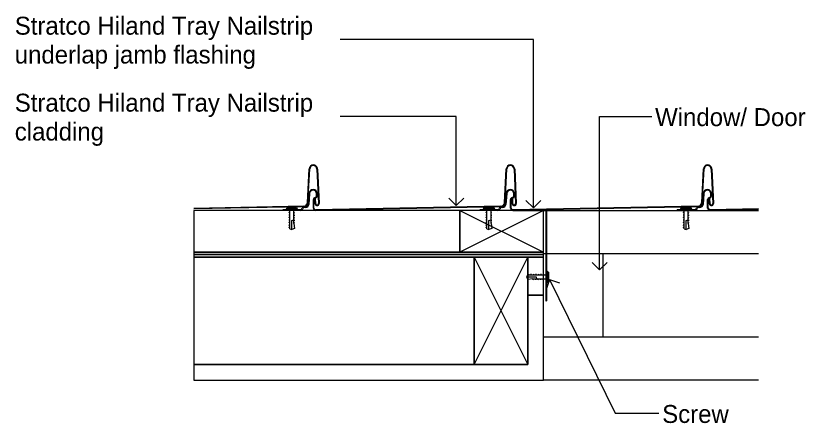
# Model space of a CAD drawing. Extents: x -2.36 to 6.66, y -3.72 to 4.13.
# Drawn here: x 5.189 to 5.85, y -2.178 to -1.837 of the extents above; entities that cross this region are included whole.
import ezdxf

# ---------------------------------------------------------------- set-up
doc = ezdxf.new("R2010")
doc.units = 0
for name, color, linetype in [('A-____-____-IDEN', 7, 'Continuous'), ('A-DETL-____-MEDM', 7, 'Continuous'), ('A-DETL-GENF-OTLN', 7, 'Continuous'), ('A-GLAZ-____-MCUT', 7, 'Continuous'), ('A-GLAZ-____-OTLN', 7, 'Continuous'), ('A-WALL-____-MCUT', 7, 'Continuous'), ('A-WALL-____-OTLN', 7, 'Continuous'), ('A-WALL-____-PATT', 7, 'Continuous'), ('A-WALL-FNSH-MCUT', 7, 'Continuous')]:
    doc.layers.add(name, color=color, linetype=linetype)

# ---------------------------------------------------------------- blocks, each defined once
blk = doc.blocks.new('Fixed - 1L _AUS_ - 1515-V21-Detail Flashings - Hiland Nailstrip Jambs')
at = {"layer": 'A-GLAZ-____-MCUT'}
for p, q in [((0.99117, 0.035), (0.99117, -0.035)), ((0.99117, 0.035), (1.04117, 0.035)), ((1.04117, -0.035), (0.99117, -0.035))]:
    blk.add_line(p, q, dxfattribs=at)
at = {"layer": 'A-GLAZ-____-OTLN'}
for p, q in [((0.86098, 0.035), (0.99117, 0.035)), ((0.99117, -0.035), (0.86098, -0.035))]:
    blk.add_line(p, q, dxfattribs=at)
blk = doc.blocks.new('DET_ST_Framing Detail Timber - 35x70 Batten-Detail Flashings - Hiland Nailstrip Jambs')
at = {"layer": 'A-DETL-____-MEDM'}
for p, q in [((0.07, 0.035), (0, 0.035)), ((0, 0.035), (0, 0)), ((0.07, 0), (0.07, 0.035)), ((0, 0), (0.07, 0))]:
    blk.add_line(p, q, dxfattribs=at)
at = {"layer": 'A-DETL-GENF-OTLN'}
for p, q in [((0, 0.035), (0.07, 0)), ((0.07, 0.035), (0, 0))]:
    blk.add_line(p, q, dxfattribs=at)
blk = doc.blocks.new('Detail Repeating_Stratco_Hiland_Tray_Nailstrip - Rib Height 38mm_165mm Coverage-V22-Detail Flashings - Hiland Nailstrip Jambs')
at = {"layer": 'A-DETL-____-MEDM'}
for p, q in [((1.33071, 0), (1.34557, 0)), ((1.34557, 0), (1.34557, -0.0005)), ((1.49571, 0), (1.51057, 0)), ((1.51057, 0), (1.51057, -0.0005)), ((1.27731, -0.00079), (1.31797, 0)), ((1.27731, -0.00129), (1.31798, -0.0005)), ((1.31648, -0.03459), (1.31517, -0.0057)), ((1.31698, -0.03457), (1.31567, -0.00568)), ((1.31801, -0.00561), (1.31813, -0.00979)), ((1.31851, -0.0056), (1.31863, -0.00977)), ((1.3195, -0.002), (1.3195, -0.00924)), ((1.32, -0.002), (1.32, -0.00924)), ((1.3245, -0.00635), (1.32302, -0.03464)), ((1.32314, -0.01418), (1.3238, -0.00504)), ((1.325, -0.00637), (1.32351, -0.03466)), ((1.32363, -0.01422), (1.32429, -0.00508)), ((1.32662, -0.00241), (1.32757, -0.00241)), ((1.32662, -0.00291), (1.32757, -0.00291)), ((1.328, -0.00303), (1.48297, 0)), ((1.328, -0.00353), (1.48298, -0.0005)), ((1.33071, -0.0005), (1.34557, -0.0005)), ((1.4845, -0.002), (1.4845, -0.00924)), ((1.485, -0.002), (1.485, -0.00924)), ((1.48814, -0.01418), (1.4888, -0.00504)), ((1.48863, -0.01422), (1.48929, -0.00508)), ((1.49162, -0.00241), (1.49257, -0.00241)), ((1.49162, -0.00291), (1.49257, -0.00291)), ((1.49571, -0.0005), (1.51057, -0.0005)), ((1.31679, -0.01206), (1.31679, -0.01397)), ((1.31729, -0.01206), (1.31729, -0.01397)), ((1.31863, -0.00977), (1.31813, -0.00979)), ((1.48179, -0.01206), (1.48179, -0.01397)), ((1.48229, -0.01206), (1.48229, -0.01397))]:
    blk.add_line(p, q, dxfattribs=at)
for centre, radius, start, end in [((1.318, -0.002), 0.002, 360, 90), ((1.33071, -0.0019), 0.0019, 90, 165.08957), ((1.483, -0.002), 0.002, 360, 90), ((1.49571, -0.0019), 0.0019, 90, 165.08957), ((1.31684, -0.00565), 0.00167, 91.69561, 181.73842), ((1.31684, -0.00565), 0.00117, 91.68553, 181.57145), ((1.31684, -0.00565), 0.00167, 1.72718, 91.74264), ((1.31684, -0.00565), 0.00117, 1.72718, 91.75272), ((1.318, -0.002), 0.0015, 0, 90), ((1.32662, -0.00525), 0.00283, 90, 175.86847), ((1.32662, -0.00525), 0.00233, 90, 175.86847), ((1.32799, -0.00653), 0.0035, 89.8838, 176.99932), ((1.32799, -0.00653), 0.003, 89.8838, 173.99932), ((1.32757, -0.00107), 0.00135, 270, 345.08957), ((1.32757, -0.00107), 0.00185, 270, 345.08957), ((1.33071, -0.0019), 0.0014, 90, 165.08957), ((1.483, -0.002), 0.0015, 0, 90), ((1.49162, -0.00525), 0.00283, 90, 175.86847), ((1.49162, -0.00525), 0.00233, 90, 175.86847), ((1.49257, -0.00107), 0.00135, 270, 345.08957), ((1.49257, -0.00107), 0.00185, 270, 345.08957), ((1.49571, -0.0019), 0.0014, 90, 165.08957), ((1.31869, -0.01206), 0.0019, 97.16746, 180), ((1.31869, -0.01206), 0.0014, 99.15451, 180), ((1.31856, -0.00924), 0.000939, 263.63492, 0), ((1.31856, -0.00924), 0.00144, 266.42376, 0), ((1.48369, -0.01206), 0.0019, 97.16746, 180), ((1.48369, -0.01206), 0.0014, 99.15451, 180), ((1.48356, -0.00924), 0.000939, 263.63492, 0), ((1.48356, -0.00924), 0.00144, 266.42376, 0), ((1.32022, -0.01397), 0.00342, 180, 355.86847), ((1.32022, -0.01397), 0.00292, 180, 355.86847), ((1.48522, -0.01397), 0.00342, 180, 355.86847), ((1.48522, -0.01397), 0.00292, 180, 355.86847), ((1.32, -0.03448), 0.00352, 181.72283, 271.72823), ((1.32, -0.03448), 0.00302, 181.65349, 271.72911), ((1.32, -0.03448), 0.00302, 271.71675, 356.99932), ((1.32, -0.03448), 0.00352, 271.71763, 356.99932)]:
    blk.add_arc(centre, radius, start, end, dxfattribs=at)
at = {"layer": 'A-DETL-GENF-OTLN'}
for p, q in [((1.33568, 0.01509), (1.338, 0.01594)), ((1.33625, 0.01102), (1.33568, 0.01509)), ((1.338, 0.01594), (1.338, 0.00832)), ((1.33975, 0.0153), (1.338, 0.01594)), ((1.33975, 0.0153), (1.33975, 0.00022)), ((1.33975, 0.0146), (1.3405, 0.01436)), ((1.50068, 0.01509), (1.503, 0.01594)), ((1.50125, 0.01102), (1.50068, 0.01509)), ((1.503, 0.01594), (1.503, 0.00832)), ((1.50475, 0.0153), (1.503, 0.01594)), ((1.50475, 0.0153), (1.50475, 0.00022)), ((1.50475, 0.0146), (1.5055, 0.01436)), ((1.3355, 0.01068), (1.33625, 0.01044)), ((1.3355, 0.00858), (1.33625, 0.00834)), ((1.33625, 0.01102), (1.33625, 0.00022)), ((1.338, 0.00832), (1.33625, 0.00782)), ((1.33975, 0.0125), (1.3405, 0.01226)), ((1.33975, 0.0104), (1.3405, 0.01016)), ((1.33975, 0.0083), (1.3405, 0.00807)), ((1.5005, 0.01068), (1.50125, 0.01044)), ((1.5005, 0.00858), (1.50125, 0.00834)), ((1.50125, 0.01102), (1.50125, 0.00022)), ((1.503, 0.00832), (1.50125, 0.00782)), ((1.50475, 0.0125), (1.5055, 0.01226)), ((1.50475, 0.0104), (1.5055, 0.01016)), ((1.50475, 0.0083), (1.5055, 0.00807)), ((1.3355, 0.00648), (1.33625, 0.00624)), ((1.3355, 0.00438), (1.33625, 0.00414)), ((1.3355, 0.00228), (1.33625, 0.00205)), ((1.33975, 0.00621), (1.3405, 0.00597)), ((1.33975, 0.00411), (1.3405, 0.00387)), ((1.33975, 0.00201), (1.3405, 0.00177)), ((1.5005, 0.00648), (1.50125, 0.00624)), ((1.5005, 0.00438), (1.50125, 0.00414)), ((1.5005, 0.00228), (1.50125, 0.00205)), ((1.50475, 0.00621), (1.5055, 0.00597)), ((1.50475, 0.00411), (1.5055, 0.00387)), ((1.50475, 0.00201), (1.5055, 0.00177)), ((1.33399, -0.00222), (1.33344, -0.00128)), ((1.33345, -0.00129), (1.34255, -0.00129)), ((1.3421, -0.00058), (1.3339, -0.00058)), ((1.34201, -0.00222), (1.33399, -0.00222)), ((1.34255, -0.00129), (1.34201, -0.00222)), ((1.49899, -0.00222), (1.49844, -0.00128)), ((1.49845, -0.00129), (1.50755, -0.00129)), ((1.5071, -0.00058), (1.4989, -0.00058)), ((1.50701, -0.00222), (1.49899, -0.00222)), ((1.50755, -0.00129), (1.50701, -0.00222))]:
    blk.add_line(p, q, dxfattribs=at)
for centre, radius, start, end in [((1.33545, 0.00022), 0.0008, 270, 360), ((1.34055, 0.00022), 0.0008, 180, 270), ((1.50045, 0.00022), 0.0008, 270, 360), ((1.50555, 0.00022), 0.0008, 180, 270), ((1.3339, -0.00108), 0.0005, 90, 203.66982), ((1.3421, -0.00108), 0.0005, 336.33018, 90), ((1.4989, -0.00108), 0.0005, 90, 203.66982), ((1.5071, -0.00108), 0.0005, 336.33018, 90)]:
    blk.add_arc(centre, radius, start, end, dxfattribs=at)
blk = doc.blocks.new('Detail Repeating_Stratco_Hiland_Tray_Nailstrip - Rib Height 38mm_165mm Coverage-V23-Detail Flashings - Hiland Nailstrip Jambs')
at = {"layer": 'A-DETL-____-MEDM'}
for p, q in [((0.17571, 0), (0.19057, 0)), ((0.19057, 0), (0.19057, -0.0005)), ((-0.00352, -0.03459), (-0.00483, -0.0057)), ((-0.00302, -0.03457), (-0.00433, -0.00568)), ((-0.00199, -0.00561), (-0.00187, -0.00979)), ((-0.00149, -0.0056), (-0.00137, -0.00977)), ((0.0045, -0.00635), (0.00302, -0.03464)), ((0.005, -0.00637), (0.00351, -0.03466)), ((0.008, -0.00303), (0.16297, 0)), ((0.008, -0.00353), (0.16298, -0.0005)), ((0.16148, -0.03459), (0.16017, -0.0057)), ((0.16198, -0.03457), (0.16067, -0.00568)), ((0.16301, -0.00561), (0.16313, -0.00979)), ((0.16351, -0.0056), (0.16363, -0.00977)), ((0.1645, -0.002), (0.1645, -0.00924)), ((0.165, -0.002), (0.165, -0.00924)), ((0.1695, -0.00635), (0.16802, -0.03464)), ((0.16814, -0.01418), (0.1688, -0.00504)), ((0.17, -0.00637), (0.16851, -0.03466)), ((0.16863, -0.01422), (0.16929, -0.00508)), ((0.17162, -0.00241), (0.17257, -0.00241)), ((0.17162, -0.00291), (0.17257, -0.00291)), ((0.173, -0.00303), (0.26495, -0.00123)), ((0.173, -0.00353), (0.26495, -0.00173)), ((0.17571, -0.0005), (0.19057, -0.0005)), ((-0.00137, -0.00977), (-0.00187, -0.00979)), ((0.16179, -0.01206), (0.16179, -0.01397)), ((0.16229, -0.01206), (0.16229, -0.01397)), ((0.16363, -0.00977), (0.16313, -0.00979))]:
    blk.add_line(p, q, dxfattribs=at)
for centre, radius, start, end in [((0.163, -0.002), 0.002, 360, 90), ((0.17571, -0.0019), 0.0019, 90, 165.08957), ((-0.00316, -0.00565), 0.00167, 91.69561, 181.73842), ((-0.00316, -0.00565), 0.00117, 91.68553, 181.57145), ((-0.00316, -0.00565), 0.00167, 1.72718, 91.74264), ((-0.00316, -0.00565), 0.00117, 1.72718, 91.75272), ((0.00799, -0.00653), 0.0035, 89.8838, 176.99932), ((0.00799, -0.00653), 0.003, 89.8838, 173.99932), ((0.16184, -0.00565), 0.00167, 91.69561, 181.73842), ((0.16184, -0.00565), 0.00117, 91.68553, 181.57145), ((0.16184, -0.00565), 0.00167, 1.72718, 91.74264), ((0.16184, -0.00565), 0.00117, 1.72718, 91.75272), ((0.163, -0.002), 0.0015, 360, 90), ((0.17162, -0.00525), 0.00283, 90, 175.86847), ((0.17162, -0.00525), 0.00233, 90, 175.86847), ((0.17299, -0.00653), 0.0035, 89.8838, 176.99932), ((0.17299, -0.00653), 0.003, 89.8838, 173.99932), ((0.17257, -0.00107), 0.00135, 270, 345.08957), ((0.17257, -0.00107), 0.00185, 270, 345.08957), ((0.17571, -0.0019), 0.0014, 90, 165.08957), ((0.16369, -0.01206), 0.0019, 97.16746, 180), ((0.16369, -0.01206), 0.0014, 99.15451, 180), ((0.16356, -0.00924), 0.000939, 263.63492, 0), ((0.16356, -0.00924), 0.00144, 266.42376, 0), ((0.16522, -0.01397), 0.00342, 180, 355.86847), ((0.16522, -0.01397), 0.00292, 180, 355.86847), ((0, -0.03448), 0.00352, 181.72283, 271.72823), ((0, -0.03448), 0.00302, 181.65349, 271.72911), ((0, -0.03448), 0.00302, 271.71675, 356.99932), ((0, -0.03448), 0.00352, 271.71763, 356.99932), ((0.165, -0.03448), 0.00352, 181.72283, 271.72823), ((0.165, -0.03448), 0.00302, 181.65349, 271.72911), ((0.165, -0.03448), 0.00302, 271.71675, 356.99932), ((0.165, -0.03448), 0.00352, 271.71763, 356.99932)]:
    blk.add_arc(centre, radius, start, end, dxfattribs=at)
at = {"layer": 'A-DETL-GENF-OTLN'}
for p, q in [((0.18068, 0.01509), (0.183, 0.01594)), ((0.18125, 0.01102), (0.18068, 0.01509)), ((0.183, 0.01594), (0.183, 0.00832)), ((0.18475, 0.0153), (0.183, 0.01594)), ((0.18475, 0.0153), (0.18475, 0.00022)), ((0.18475, 0.0146), (0.1855, 0.01436)), ((0.1805, 0.01068), (0.18125, 0.01044)), ((0.1805, 0.00858), (0.18125, 0.00834)), ((0.18125, 0.01102), (0.18125, 0.00022)), ((0.183, 0.00832), (0.18125, 0.00782)), ((0.18475, 0.0125), (0.1855, 0.01226)), ((0.18475, 0.0104), (0.1855, 0.01016)), ((0.18475, 0.0083), (0.1855, 0.00807)), ((0.1805, 0.00648), (0.18125, 0.00624)), ((0.1805, 0.00438), (0.18125, 0.00414)), ((0.1805, 0.00228), (0.18125, 0.00205)), ((0.18475, 0.00621), (0.1855, 0.00597)), ((0.18475, 0.00411), (0.1855, 0.00387)), ((0.18475, 0.00201), (0.1855, 0.00177)), ((0.17899, -0.00222), (0.17844, -0.00128)), ((0.17845, -0.00129), (0.18755, -0.00129)), ((0.1871, -0.00058), (0.1789, -0.00058)), ((0.18701, -0.00222), (0.17899, -0.00222)), ((0.18755, -0.00129), (0.18701, -0.00222))]:
    blk.add_line(p, q, dxfattribs=at)
for centre, radius, start, end in [((0.18045, 0.00022), 0.0008, 270, 360), ((0.18555, 0.00022), 0.0008, 180, 270), ((0.1789, -0.00108), 0.0005, 90, 203.66982), ((0.1871, -0.00108), 0.0005, 336.33018, 90)]:
    blk.add_arc(centre, radius, start, end, dxfattribs=at)
blk = doc.blocks.new('DET_ST_Framing Detail Timber - 45x90-Detail Flashings - Hiland Nailstrip Jambs')
at = {"layer": 'A-DETL-____-MEDM'}
for p, q in [((0.09, 0.045), (0, 0.045)), ((0, 0.045), (0, 0)), ((0.09, 0), (0.09, 0.045)), ((0, 0), (0.09, 0))]:
    blk.add_line(p, q, dxfattribs=at)
at = {"layer": 'A-DETL-GENF-OTLN'}
for p, q in [((0, 0.045), (0.09, 0)), ((0.09, 0.045), (0, 0))]:
    blk.add_line(p, q, dxfattribs=at)
blk = doc.blocks.new('DET_Screw Metal Wafer - DET_Screw Metal Wafer-Detail Flashings - Hiland Nailstrip Jambs')
at = {"layer": 'A-DETL-GENF-OTLN'}
for p, q in [((-0.00455, 0.00071), (-0.00401, 0.00164)), ((0.00455, 0.00071), (-0.00455, 0.00071)), ((-0.00401, 0.00164), (0.00401, 0.00164)), ((0.00401, 0.00164), (0.00456, 0.0007)), ((-0.0041, 0), (0.0041, 0)), ((-0.00175, -0.00259), (-0.0025, -0.00235)), ((-0.00175, -0.00468), (-0.0025, -0.00445)), ((-0.00175, -0.00678), (-0.0025, -0.00654)), ((-0.00175, -0.01588), (-0.00175, -0.0008)), ((0.00175, -0.0116), (0.00175, -0.0008)), ((0.0025, -0.00286), (0.00175, -0.00262)), ((0.0025, -0.00496), (0.00175, -0.00472)), ((-0.00175, -0.00888), (-0.0025, -0.00864)), ((-0.00175, -0.01098), (-0.0025, -0.01074)), ((-0.00175, -0.01308), (-0.0025, -0.01284)), ((0, -0.0089), (0.00175, -0.0084)), ((0, -0.01651), (0, -0.0089)), ((0.0025, -0.00706), (0.00175, -0.00682)), ((0.0025, -0.00915), (0.00175, -0.00892)), ((0.0025, -0.01125), (0.00175, -0.01102)), ((0.00175, -0.0116), (0.00232, -0.01567)), ((-0.00175, -0.01518), (-0.0025, -0.01494)), ((-0.00175, -0.01588), (0, -0.01651)), ((0.00232, -0.01567), (0, -0.01651))]:
    blk.add_line(p, q, dxfattribs=at)
for centre, radius, start, end in [((-0.0041, 0.0005), 0.0005, 156.33018, 270), ((-0.00255, -0.0008), 0.0008, 360, 90), ((0.00255, -0.0008), 0.0008, 90, 180), ((0.0041, 0.0005), 0.0005, 270, 23.66982)]:
    blk.add_arc(centre, radius, start, end, dxfattribs=at)
blk = doc.blocks.new('Detail_Stratco_Hiland_Tray_Nailstrip_Underlap Jamb - Rib Height 25mm-Detail Flashings - Hiland Nailstrip Jambs')
at = {"layer": 'A-DETL-GENF-OTLN'}
for p, q in [((-0.11272, -0.11466), (-0.11338, -0.1238)), ((-0.11222, -0.11469), (-0.11288, -0.12384)), ((-0.10638, -0.11682), (-0.10638, -0.11491)), ((-0.10588, -0.11682), (-0.10588, -0.11491)), ((-0.10909, -0.12688), (-0.10909, -0.11964)), ((-0.10859, -0.12688), (-0.10859, -0.11964)), ((-0.1198, -0.12838), (-0.13465, -0.12838)), ((-0.13465, -0.12888), (-0.13465, -0.12838)), ((-0.1198, -0.12888), (-0.13465, -0.12888)), ((-0.13164, -0.12759), (-0.13109, -0.12666)), ((-0.12254, -0.12759), (-0.13164, -0.12759)), ((-0.13119, -0.1283), (-0.12299, -0.1283)), ((-0.13109, -0.12666), (-0.12308, -0.12666)), ((-0.12884, -0.13089), (-0.12959, -0.13065)), ((-0.12884, -0.14418), (-0.12884, -0.1291)), ((-0.12534, -0.1399), (-0.12534, -0.1291)), ((-0.12459, -0.13116), (-0.12534, -0.13092)), ((-0.12308, -0.12666), (-0.12253, -0.1276)), ((-0.11571, -0.12596), (-0.11666, -0.12596)), ((-0.11571, -0.12646), (-0.11666, -0.12646)), ((-0.10709, -0.12838), (-0.07909, -0.12838)), ((-0.10709, -0.12888), (-0.07959, -0.12888)), ((-0.07959, -0.12888), (-0.07959, -0.20438)), ((-0.07909, -0.12838), (-0.07909, -0.20438)), ((-0.12884, -0.13299), (-0.12959, -0.13275)), ((-0.12884, -0.13508), (-0.12959, -0.13485)), ((-0.12884, -0.13718), (-0.12959, -0.13694)), ((-0.12709, -0.1372), (-0.12534, -0.1367)), ((-0.12709, -0.14482), (-0.12709, -0.1372)), ((-0.12459, -0.13326), (-0.12534, -0.13302)), ((-0.12459, -0.13536), (-0.12534, -0.13512)), ((-0.12459, -0.13746), (-0.12534, -0.13722)), ((-0.12884, -0.13928), (-0.12959, -0.13904)), ((-0.12884, -0.14138), (-0.12959, -0.14114)), ((-0.12884, -0.14348), (-0.12959, -0.14324)), ((-0.12884, -0.14418), (-0.12709, -0.14482)), ((-0.12477, -0.14397), (-0.12709, -0.14482)), ((-0.12459, -0.13955), (-0.12534, -0.13932)), ((-0.12534, -0.1399), (-0.12477, -0.14397)), ((-0.07959, -0.20438), (-0.07909, -0.20438))]:
    blk.add_line(p, q, dxfattribs=at)
for centre, radius, start, end in [((-0.10931, -0.11491), 0.00342, 0, 175.86847), ((-0.10931, -0.11491), 0.00292, 0, 175.86847), ((-0.10765, -0.11964), 0.00144, 86.42376, 180), ((-0.10765, -0.11964), 0.000939, 83.63492, 180), ((-0.10778, -0.11682), 0.0014, 279.15451, 0), ((-0.10778, -0.11682), 0.0019, 277.16746, 0), ((-0.11571, -0.12363), 0.00233, 270, 355.86847), ((-0.11571, -0.12363), 0.00283, 270, 355.86847), ((-0.13119, -0.1278), 0.0005, 156.33018, 270), ((-0.12964, -0.1291), 0.0008, 0, 90), ((-0.12454, -0.1291), 0.0008, 90, 180), ((-0.12299, -0.1278), 0.0005, 270, 23.66982), ((-0.1198, -0.12697), 0.0014, 270, 345.08957), ((-0.1198, -0.12697), 0.0019, 270, 345.08957), ((-0.11666, -0.12781), 0.00185, 90, 165.08957), ((-0.11666, -0.12781), 0.00135, 90, 165.08957), ((-0.10709, -0.12688), 0.002, 180, 270), ((-0.10709, -0.12688), 0.0015, 180, 270)]:
    blk.add_arc(centre, radius, start, end, dxfattribs=at)

msp = doc.modelspace()

# ---------------------------------------------------------------- linework, layer by layer
at = {"layer": 'A-____-____-IDEN'}
for p, q in [((5.62253, -1.85701), (5.46069, -1.85701)), ((5.62253, -1.99795), (5.62253, -1.85701)), ((5.55802, -1.92138), (5.46069, -1.92138)), ((5.55802, -1.99598), (5.55802, -1.92138)), ((5.67798, -1.92138), (5.72168, -1.92138)), ((5.67798, -2.04983), (5.67798, -1.92138)), ((5.55802, -1.99598), (5.55177, -1.98973)), ((5.55802, -1.99598), (5.56427, -1.98973)), ((5.62253, -1.99795), (5.61628, -1.9917)), ((5.62253, -1.99795), (5.62878, -1.9917)), ((5.67798, -2.04983), (5.67173, -2.04358)), ((5.67798, -2.04983), (5.68423, -2.04358)), ((5.63613, -2.05774), (5.63326, -2.0661)), ((5.63613, -2.05774), (5.64449, -2.0606)), ((5.63613, -2.05774), (5.69092, -2.16966)), ((5.69092, -2.16966), (5.72764, -2.16966))]:
    msp.add_line(p, q, dxfattribs=at)
at = {"layer": 'A-WALL-____-MCUT'}
for p, q in [((5.56087, -2), (5.33841, -2)), ((5.56087, -2.035), (5.33841, -2.035)), ((5.63087, -2.037), (5.33841, -2.037)), ((5.57283, -2.039), (5.33841, -2.039)), ((5.63087, -2.039), (5.61783, -2.039)), ((5.63087, -2.071), (5.63087, -2.035)), ((5.63087, -2.071), (5.61787, -2.071)), ((5.33841, -2.129), (5.57283, -2.129))]:
    msp.add_line(p, q, dxfattribs=at)
at = {"layer": 'A-WALL-____-OTLN'}
for p, q in [((5.63087, -2), (5.81106, -2)), ((5.81106, -2.142), (5.63087, -2.142))]:
    msp.add_line(p, q, dxfattribs=at)
at = {"layer": 'A-WALL-____-PATT'}
for p, q in [((5.56087, -2), (5.33841, -2)), ((5.33841, -2), (5.33841, -2.035)), ((5.56087, -2.035), (5.56087, -2)), ((5.33841, -2.035), (5.56087, -2.035)), ((5.63087, -2.035), (5.33841, -2.035)), ((5.33841, -2.035), (5.33841, -2.03625)), ((5.33841, -2.03625), (5.33841, -2.037)), ((5.33841, -2.037), (5.63087, -2.037)), ((5.63087, -2.037), (5.33841, -2.037)), ((5.33841, -2.037), (5.33841, -2.039)), ((5.33841, -2.039), (5.57283, -2.039)), ((5.57283, -2.039), (5.33841, -2.039)), ((5.33841, -2.039), (5.33841, -2.108)), ((5.57283, -2.039), (5.63087, -2.039)), ((5.57283, -2.129), (5.57283, -2.039)), ((5.63087, -2.039), (5.61783, -2.039)), ((5.61783, -2.039), (5.61783, -2.129)), ((5.63087, -2.037), (5.63087, -2.035)), ((5.63087, -2.039), (5.63087, -2.037)), ((5.63087, -2.071), (5.63087, -2.039)), ((5.61787, -2.071), (5.61783, -2.129)), ((5.61787, -2.129), (5.61787, -2.071)), ((5.61787, -2.071), (5.63087, -2.071)), ((5.63087, -2.071), (5.61787, -2.071)), ((5.63087, -2.142), (5.63087, -2.071)), ((5.33841, -2.108), (5.33841, -2.129)), ((5.33841, -2.129), (5.57283, -2.129)), ((5.61783, -2.129), (5.33841, -2.129)), ((5.33841, -2.129), (5.33841, -2.142)), ((5.61783, -2.129), (5.61787, -2.129)), ((5.61783, -2.129), (5.61783, -2.129)), ((5.33841, -2.142), (5.63087, -2.142))]:
    msp.add_line(p, q, dxfattribs=at)
at = {"layer": 'A-WALL-FNSH-MCUT'}
for p, q in [((5.63087, -2.142), (5.63087, -2.071)), ((5.33841, -2.142), (5.63087, -2.142))]:
    msp.add_line(p, q, dxfattribs=at)

# ---------------------------------------------------------------- block references
at = {"layer": 'A-DETL-GENF-OTLN'}
for name, p, rotation in [('Detail Repeating_Stratco_Hiland_Tray_Nailstrip - Rib Height 38mm_165mm Coverage-V23-Detail Flashings - Hiland Nailstrip Jambs', (5.60337, -2), 180), ('Detail Repeating_Stratco_Hiland_Tray_Nailstrip - Rib Height 38mm_165mm Coverage-V22-Detail Flashings - Hiland Nailstrip Jambs', (7.08837, -2), 180), ('DET_ST_Framing Detail Timber - 45x90-Detail Flashings - Hiland Nailstrip Jambs', (5.61783, -2.129), 89.9999999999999), ('DET_Screw Metal Wafer - DET_Screw Metal Wafer-Detail Flashings - Hiland Nailstrip Jambs', (5.63362, -2.05553), -90.00000000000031)]:
    msp.add_blockref(name, p, dxfattribs=dict(at, rotation=rotation))
for name, p in [('Detail_Stratco_Hiland_Tray_Nailstrip_Underlap Jamb - Rib Height 25mm-Detail Flashings - Hiland Nailstrip Jambs', (5.71246, -1.87112)), ('DET_ST_Framing Detail Timber - 35x70 Batten-Detail Flashings - Hiland Nailstrip Jambs', (5.56087, -2.035))]:
    msp.add_blockref(name, p, dxfattribs=at)
at = {"layer": 'A-GLAZ-____-OTLN', "rotation": 180}
msp.add_blockref('Fixed - 1L _AUS_ - 1515-V21-Detail Flashings - Hiland Nailstrip Jambs', (6.67204, -2.071), dxfattribs=at)

# ---------------------------------------------------------------- texts
at = {"layer": 'A-____-____-IDEN'}
for s, p in [('Stratco Hiland Tray Nailstrip', (5.18849, -1.85303)), ('underlap jamb flashing', (5.18849, -1.87717)), ('Stratco Hiland Tray Nailstrip', (5.18849, -1.9174)), ('Window/ Door', (5.7244, -1.92948)), ('cladding', (5.18849, -1.94155)), ('Screw', (5.73035, -2.17776))]:
    msp.add_text(s, height=0.015, dxfattribs=at).set_placement(p)

doc.saveas('drawing.dxf')
